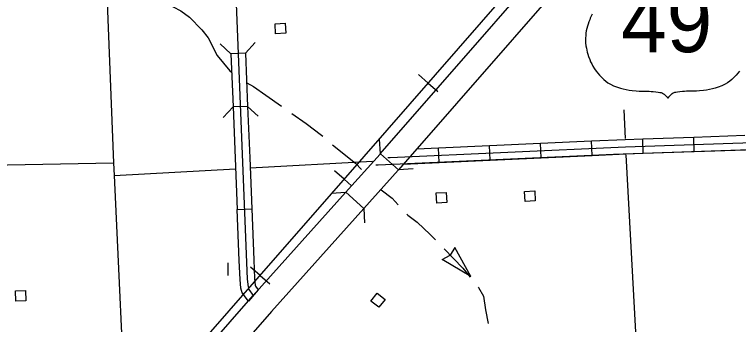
# Model space of a CAD drawing. Extents: x -0.3 to 2.65, y 0 to 1.9.
# Drawn here: x 0.4946 to 0.5841, y 0.3259 to 0.3643 of the extents above; entities that cross this region are included whole.
import ezdxf

# ---------------------------------------------------------------- set-up
doc = ezdxf.new("R2010")
doc.units = 0
for name, color, linetype in [('Level 11', 7, 'Continuous'), ('Level 12', 7, 'Continuous'), ('Level 14', 7, 'Continuous'), ('Level 15', 7, 'Continuous'), ('Level 18', 7, 'Continuous'), ('Level 19', 7, 'Continuous'), ('Level 20', 7, 'Continuous'), ('Level 26', 7, 'Continuous'), ('Level 27', 7, 'Continuous'), ('Level 28', 7, 'Continuous'), ('Level 29', 7, 'Continuous'), ('Level 30', 7, 'Continuous')]:
    doc.layers.add(name, color=color, linetype=linetype)

msp = doc.modelspace()

# ---------------------------------------------------------------- linework, layer by layer
at = {"layer": 'Level 11'}
msp.add_lwpolyline([(0.504492, 0.406507), (0.50687, 0.345942), (0.506939, 0.344348), (0.508479, 0.311585), (0.508504, 0.311117)], dxfattribs=at)
at = {"layer": 'Level 12'}
for p, q in [((0.549064, 0.335466), (0.548496, 0.334533)), ((0.551033, 0.331862), (0.549064, 0.335466)), ((0.547526, 0.333999), (0.548485, 0.334523)), ((0.551033, 0.331862), (0.547526, 0.333999))]:
    msp.add_line(p, q, dxfattribs=at)
for points in [[(0.523363, 0.35583), (0.524188, 0.355369), (0.525696, 0.354282)], [(0.525696, 0.354282), (0.527638, 0.352925)], [(0.528933, 0.352021), (0.53071, 0.35078), (0.532579, 0.349361), (0.532748, 0.349213)], [(0.533939, 0.348175), (0.536778, 0.345883), (0.537525, 0.345089)], [(0.53996, 0.342612), (0.539987, 0.342589), (0.541324, 0.341579), (0.542054, 0.340725)], [(0.543139, 0.339578), (0.54326, 0.339454), (0.544411, 0.338592), (0.546045, 0.337091), (0.546672, 0.336434)], [(0.547762, 0.335291), (0.550048, 0.332895), (0.550955, 0.331793)], [(0.551959, 0.330574), (0.551995, 0.330531), (0.552629, 0.329441), (0.552847, 0.327745), (0.553212, 0.326072)]]:
    msp.add_lwpolyline(points, dxfattribs=at)
at = {"layer": 'Level 14'}
msp.add_lwpolyline([(0.501512, 0.37265), (0.501826, 0.372579), (0.503124, 0.372481), (0.503856, 0.372165), (0.504511, 0.371977), (0.505292, 0.371351), (0.506147, 0.370428), (0.506766, 0.369963), (0.507596, 0.369579), (0.508952, 0.368426), (0.510426, 0.367025), (0.511301, 0.366728), (0.512111, 0.366535), (0.513296, 0.365723), (0.515219, 0.364739), (0.516271, 0.363932), (0.517812, 0.362367), (0.518598, 0.361368), (0.519687, 0.359182), (0.521254, 0.357305), (0.521452, 0.357123)], dxfattribs=at)
at = {"layer": 'Level 15'}
for p, q in [((0.578679, 0.347327), (0.578619, 0.349121)), ((0.559752, 0.34656), (0.559669, 0.348353)), ((0.566064, 0.346852), (0.565981, 0.348645)), ((0.572365, 0.347116), (0.572305, 0.34891)), ((0.547129, 0.345976), (0.547046, 0.347769)), ((0.553441, 0.346268), (0.553358, 0.348061))]:
    msp.add_line(p, q, dxfattribs=at)
for points in [[(0.520188, 0.408264), (0.52158, 0.37696), (0.523421, 0.331562), (0.52351, 0.330617), (0.523609, 0.330273), (0.524156, 0.32954)], [(0.540777, 0.346596), (0.541093, 0.346578), (0.570174, 0.347924), (0.619677, 0.349583), (0.642729, 0.35053), (0.673859, 0.351282), (0.68769, 0.351749), (0.723776, 0.353332), (0.724783, 0.353569), (0.726082, 0.353422), (0.756571, 0.355154), (0.790651, 0.356889), (0.80184, 0.357528), (0.802553, 0.357656), (0.802894, 0.357791), (0.80317, 0.358067), (0.803305, 0.35853), (0.803339, 0.35912), (0.803079, 0.364173)], [(0.539301, 0.345687), (0.539616, 0.34567), (0.568697, 0.347015), (0.6182, 0.348675), (0.641252, 0.349622), (0.672382, 0.350374), (0.686213, 0.350841), (0.722299, 0.352424), (0.723306, 0.352661), (0.724605, 0.352514), (0.755094, 0.354246), (0.789174, 0.355981), (0.800363, 0.35662), (0.801076, 0.356747), (0.801417, 0.356882), (0.801693, 0.357159), (0.801828, 0.357621), (0.801862, 0.358212), (0.801602, 0.363265)], [(0.572305, 0.34891), (0.578619, 0.349121)], [(0.578619, 0.349121), (0.584934, 0.349333)], [(0.553358, 0.348061), (0.559669, 0.348353)], [(0.559669, 0.348353), (0.565981, 0.348645)], [(0.565981, 0.348645), (0.570138, 0.348837), (0.572305, 0.34891)], [(0.544363, 0.347644), (0.547046, 0.347769)], [(0.547046, 0.347769), (0.553358, 0.348061)], [(0.572365, 0.347116), (0.578679, 0.347327)], [(0.578679, 0.347327), (0.584994, 0.347539)], [(0.553441, 0.346268), (0.559752, 0.34656)], [(0.559752, 0.34656), (0.566064, 0.346852)], [(0.566064, 0.346852), (0.570209, 0.347043), (0.572365, 0.347116)], [(0.542727, 0.345772), (0.547129, 0.345976)], [(0.547129, 0.345976), (0.553441, 0.346268)], [(0.521015, 0.333563), (0.521015, 0.332021)]]:
    msp.add_lwpolyline(points, dxfattribs=at)
at = {"layer": 'Level 18'}
for p, q in [((0.52321, 0.359504), (0.521394, 0.359393)), ((0.521394, 0.359393), (0.521394, 0.359393)), ((0.52321, 0.359504), (0.52321, 0.359504)), ((0.522173, 0.340181), (0.523967, 0.340254)), ((0.522173, 0.340181), (0.522173, 0.340181))]:
    msp.add_line(p, q, dxfattribs=at)
for points in [[(0.521394, 0.359393), (0.521659, 0.352873)], [(0.523186, 0.359503), (0.523453, 0.352909)], [(0.523453, 0.352909), (0.521659, 0.352873)], [(0.521659, 0.352873), (0.521917, 0.346494)], [(0.523453, 0.352909), (0.523711, 0.346566)], [(0.521917, 0.346494), (0.522173, 0.340181)], [(0.523711, 0.346566), (0.523967, 0.340254)], [(0.522429, 0.333868), (0.522173, 0.340181)], [(0.523967, 0.340254), (0.524223, 0.333941)], [(0.524223, 0.333941), (0.524317, 0.331622), (0.524396, 0.330784), (0.524426, 0.330678), (0.524767, 0.330221)], [(0.523552, 0.328849), (0.522792, 0.329867), (0.522624, 0.330449), (0.522525, 0.331501), (0.522429, 0.333868)], [(0.524767, 0.330221), (0.523552, 0.328849)]]:
    msp.add_lwpolyline(points, dxfattribs=at)
at = {"layer": 'Level 19'}
for points in [[(0.526916, 0.361889), (0.526861, 0.363134), (0.528109, 0.363189), (0.528164, 0.361945)], [(0.546829, 0.340962), (0.546774, 0.342206), (0.548022, 0.342261), (0.548077, 0.341017)], [(0.557759, 0.341164), (0.557704, 0.342408), (0.558952, 0.342463), (0.559007, 0.341219)], [(0.494788, 0.328848), (0.494744, 0.330093), (0.495992, 0.330137), (0.496037, 0.328893)], [(0.539672, 0.328072), (0.538702, 0.328853), (0.539485, 0.329826), (0.540455, 0.329045)]]:
    msp.add_lwpolyline(points, close=True, dxfattribs=at)
at = {"layer": 'Level 20'}
for points in [[(0.569956, 0.352503), (0.570125, 0.348953)], [(0.570228, 0.34691), (0.571851, 0.316681)], [(0.476206, 0.345346), (0.50687, 0.345942)], [(0.523762, 0.345299), (0.538904, 0.346155)], [(0.506939, 0.344348), (0.52197, 0.345198)]]:
    msp.add_lwpolyline(points, dxfattribs=at)
at = {"layer": 'Level 26'}
for points in [[(0.566062, 0.36432), (0.565937, 0.364059), (0.565824, 0.363803), (0.565747, 0.363613), (0.565655, 0.363369), (0.565554, 0.363071), (0.565474, 0.362823), (0.565399, 0.362552), (0.56533, 0.362237), (0.565283, 0.361958), (0.56525, 0.361666), (0.565231, 0.361347), (0.56523, 0.361048), (0.565243, 0.360755), (0.565279, 0.360411), (0.565332, 0.360086), (0.565386, 0.359839), (0.565442, 0.359624), (0.565513, 0.359379), (0.565608, 0.359075), (0.565745, 0.358706), (0.565863, 0.358434), (0.565999, 0.358155), (0.56615, 0.357881), (0.566345, 0.357566), (0.566546, 0.357277), (0.566741, 0.357026), (0.566963, 0.356768), (0.567249, 0.356471), (0.567492, 0.356246), (0.567742, 0.356037)], [(0.584259, 0.357277), (0.584064, 0.357026), (0.583842, 0.356768), (0.583556, 0.356471), (0.583313, 0.356246), (0.583063, 0.356037)], [(0.567742, 0.356037), (0.568002, 0.35584), (0.568314, 0.355636), (0.568706, 0.355461), (0.569164, 0.355285), (0.569539, 0.355163), (0.569876, 0.35507), (0.570257, 0.354982), (0.570614, 0.354916), (0.570999, 0.354863), (0.571483, 0.354822), (0.571853, 0.354809), (0.57217, 0.35481), (0.572479, 0.354807), (0.572787, 0.354797), (0.57308, 0.354783), (0.573335, 0.354765), (0.573586, 0.354744), (0.573908, 0.354711), (0.574223, 0.354672), (0.574411, 0.354645), (0.574567, 0.354615), (0.574756, 0.354537), (0.574864, 0.354477), (0.574958, 0.354415), (0.575087, 0.354311), (0.57521, 0.354185), (0.575311, 0.354056), (0.575402, 0.353907)], [(0.583063, 0.356037), (0.582803, 0.35584), (0.582491, 0.355636), (0.582099, 0.355461), (0.58164, 0.355285), (0.581266, 0.355163), (0.580929, 0.35507), (0.580548, 0.354982), (0.580191, 0.354916), (0.579806, 0.354863), (0.579322, 0.354822), (0.578952, 0.354809), (0.578635, 0.35481), (0.578326, 0.354807), (0.578018, 0.354797), (0.577725, 0.354783), (0.57747, 0.354765), (0.577219, 0.354744), (0.576897, 0.354711), (0.576582, 0.354672), (0.576394, 0.354645), (0.576238, 0.354615), (0.576049, 0.354537), (0.575941, 0.354477), (0.575847, 0.354415), (0.575718, 0.354311), (0.575595, 0.354185), (0.575494, 0.354056), (0.575402, 0.353907)]]:
    msp.add_lwpolyline(points, dxfattribs=at)
at = {"layer": 'Level 27'}
for points in [[(0.539861, 0.347038), (0.596632, 0.412004), (0.623105, 0.442683)], [(0.625357, 0.440714), (0.598891, 0.410042), (0.542113, 0.34507)], [(0.539861, 0.347038), (0.53983, 0.347003), (0.535564, 0.342251)], [(0.542124, 0.345082), (0.539871, 0.34705)], [(0.542104, 0.34506), (0.542069, 0.345019), (0.537807, 0.340271)], [(0.509648, 0.312938), (0.524156, 0.32954), (0.535564, 0.342251)], [(0.535597, 0.342287), (0.537823, 0.340289)], [(0.537807, 0.340271), (0.526395, 0.327557), (0.511935, 0.311009)]]:
    msp.add_lwpolyline(points, dxfattribs=at)
at = {"layer": 'Level 28'}
for p, q in [((0.545788, 0.355798), (0.544598, 0.356836)), ((0.545788, 0.355798), (0.546978, 0.354759)), ((0.535399, 0.3439), (0.534209, 0.34494)), ((0.535399, 0.3439), (0.536306, 0.343107)), ((0.525005, 0.332007), (0.523815, 0.333046)), ((0.525005, 0.332007), (0.526194, 0.330967))]:
    msp.add_line(p, q, dxfattribs=at)
for points in [[(0.504505, 0.30855), (0.537855, 0.346711), (0.601576, 0.419694), (0.649211, 0.474499), (0.690797, 0.522238), (0.707601, 0.541644)], [(0.504505, 0.30855), (0.537855, 0.346711), (0.601576, 0.419694), (0.649211, 0.474499), (0.690797, 0.522238), (0.707601, 0.541644)], [(0.504505, 0.30855), (0.537855, 0.346711), (0.601576, 0.419694), (0.649211, 0.474499), (0.690797, 0.522238), (0.707601, 0.541644)], [(0.504505, 0.30855), (0.537855, 0.346711), (0.601576, 0.419694), (0.649211, 0.474499), (0.690797, 0.522238), (0.707601, 0.541644)], [(0.403862, 0.144274), (0.418799, 0.170533), (0.434028, 0.19722), (0.449701, 0.224836), (0.473196, 0.265996), (0.476816, 0.273032), (0.478166, 0.275494), (0.479699, 0.278204), (0.481107, 0.280392), (0.483318, 0.28357), (0.485115, 0.285916), (0.487614, 0.289069), (0.493281, 0.295769), (0.499959, 0.303335), (0.504505, 0.30855), (0.537855, 0.346711), (0.601576, 0.419694), (0.649211, 0.474499), (0.689919, 0.52123)]]:
    msp.add_lwpolyline(points, dxfattribs=at)
at = {"layer": 'Level 29'}
for points in [[(0.524404, 0.360799), (0.523187, 0.35948)], [(0.521394, 0.359407), (0.520074, 0.360624)], [(0.520442, 0.351544), (0.521662, 0.352873)], [(0.523454, 0.352906), (0.524773, 0.351682)]]:
    msp.add_lwpolyline(points, dxfattribs=at)
at = {"layer": 'Level 30'}
for points in [[(0.539871, 0.34705), (0.539751, 0.348841)], [(0.543915, 0.345202), (0.542124, 0.345082)], [(0.533805, 0.342191), (0.535597, 0.342287)], [(0.537823, 0.340289), (0.53792, 0.338497)]]:
    msp.add_lwpolyline(points, dxfattribs=at)

# ---------------------------------------------------------------- texts
at = {"layer": 'Level 26'}
msp.add_text('49', height=0.0075746, dxfattribs=at).set_placement((0.569632, 0.359607))

doc.saveas('drawing.dxf')
